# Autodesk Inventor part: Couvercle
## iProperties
Created: 2011-11
Part Number: Couvercle
Document SubType Name: Modeling
Designer: domi
Density: 1 g/cm^3
Author: domi
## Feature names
1. Extrusion1
2. Extrusion2
3. Extrusion3
4. Extrusion4
5. Extrusion5
6. Extrusion6
7. Extrusion7
8. Extrusion8
9. Extrusion9
10. Extrusion10
11. Perçage1 [Hole]
12. Perçage2 [Hole]
13. Perçage3 [Hole]
14. Perçage4 [Hole]
15. Extrusion11
16. Extrusion12
17. Chanfrein1 [Chamfer]
18. Perçage5 [Hole]
19. Perçage6 [Hole]
20. Extrusion13
21. Extrusion14
22. Extrusion15
23. Congé2 [Fillet]
24. Perçage7 [Hole]
25. Extrusion16
26. Extrusion17
27. Extrusion18
28. Extrusion19
29. Extrusion20
30. Lissage1
